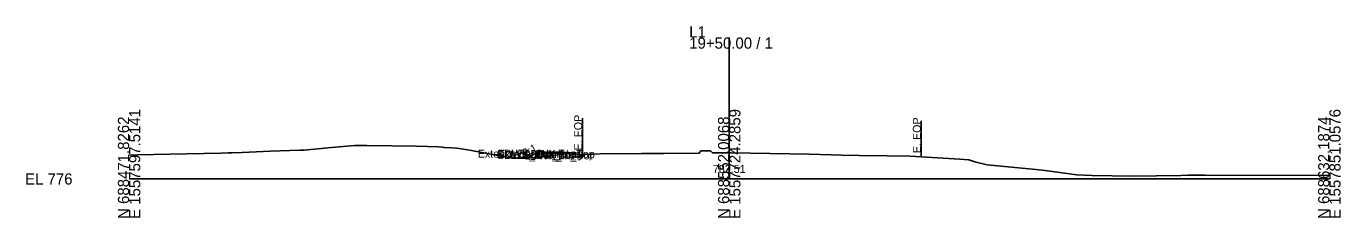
# Model space of a CAD drawing. Extents: x -26 to 2603, y -3010 to 9589.
# Drawn here: x -25.7 to 302.8, y 2990.3 to 3038.2 of the extents above; entities that cross this region are included whole.
import ezdxf

# ---------------------------------------------------------------- set-up
doc = ezdxf.new("R2010")
doc.units = 0
for name, color, linetype in [('Default', 7, 'Continuous'), ('Exist Cross Section Cell', 7, 'Continuous'), ('Exist XS Center Line Elevation Label', 7, 'Continuous'), ('Exist XS Ground Line', 7, 'Continuous'), ('Prop CMT Conc Surface', 7, 'Continuous'), ('Prop CMT Concrete Structures', 7, 'Continuous'), ('Prop CMT Slope Grass', 7, 'Continuous'), ('Prop XS Earthwork Shape', 7, 'Continuous'), ('Prop XS Label Text', 7, 'Continuous'), ('Prop XS Side Slope Text', 7, 'Continuous')]:
    doc.layers.add(name, color=color, linetype=linetype)

msp = doc.modelspace()

# ---------------------------------------------------------------- linework, layer by layer
at = {"layer": 'Exist Cross Section Cell'}
for p, q in [((150, 3000), (150, 3035.36)), ((0, 3000), (150, 3000)), ((150, 3000), (300, 3000))]:
    msp.add_line(p, q, dxfattribs=at)
at = {"layer": 'Exist XS Ground Line'}
msp.add_lwpolyline([(0, 3005.97), (2.09, 3006.03), (10.18, 3006.19), (22.96, 3006.47), (24.67, 3006.49), (25.76, 3006.5), (28.27, 3006.64), (35.25, 3006.91), (42.64, 3007.18), (43.72, 3007.22), (49.64, 3007.78), (56.33, 3008.37), (57.13, 3008.38), (57.62, 3008.37), (59.39, 3008.35), (71.81, 3008.2), (77.32, 3008.02), (78.22, 3007.98), (78.77, 3007.85), (80.71, 3007.76), (81.91, 3007.73), (84.7, 3007.26), (95.78, 3005.19), (99.32, 3005.23), (101.25, 3005.36), (101.92, 3005.36), (110.8, 3006.5), (111.27, 3006.16), (111.58, 3006.16), (113.3, 3006.13), (114.1, 3006.15), (117.73, 3006.28), (128.1, 3006.35), (130.29, 3006.36), (133.55, 3006.4), (142.5, 3006.43), (142.91, 3007.03), (143.41, 3007.03), (145.33, 3007.03), (145.82, 3006.56), (150, 3006.51), (150.48, 3006.5), (169.96, 3006.22), (178.13, 3005.98), (182.52, 3005.86), (189.43, 3005.76), (195.19, 3005.68), (196.73, 3005.6), (198, 3005.53), (207.63, 3004.93), (209.89, 3004.8), (211.43, 3004.25), (214.44, 3003.54), (226.67, 3002.4), (229.01, 3002.07), (236.86, 3001.01), (240.68, 3000.9), (250.69, 3000.72), (262.92, 3000.86), (264.75, 3000.94), (269.01, 3000.93), (286.16, 3000.87), (300, 3000.94)], dxfattribs=at)
at = {"layer": 'Prop CMT Conc Surface'}
for points in [[(108, 3006.71), (103, 3006.81)], [(111.35, 3006.01), (111.35, 3006.51), (110.85, 3006.51)], [(113.35, 3006.13), (111.35, 3006.01)]]:
    msp.add_lwpolyline(points, dxfattribs=at)
at = {"layer": 'Prop CMT Concrete Structures'}
for points in [[(103, 3006.48), (103, 3006.81)], [(108, 3006.38), (103, 3006.48)], [(108, 3006.71), (108, 3006.38)], [(110.85, 3006.51), (110.85, 3005.5), (113.35, 3005.55)], [(113.35, 3005.55), (113.35, 3006.13)]]:
    msp.add_lwpolyline(points, dxfattribs=at)
at = {"layer": 'Prop CMT Slope Grass'}
for p, q in [((102.5, 3006.82), (99.32, 3005.23)), ((103, 3006.81), (102.5, 3006.82)), ((108, 3006.71), (110.85, 3006.51))]:
    msp.add_line(p, q, dxfattribs=at)
at = {"layer": 'Prop XS Earthwork Shape'}
for points in [[(102.5, 3006.82), (99.32, 3005.23), (101.25, 3005.36), (101.92, 3005.36), (110.8, 3006.5), (110.85, 3006.46), (110.85, 3006.51), (108, 3006.71), (108, 3006.38), (103, 3006.48), (103, 3006.81)], [(110.85, 3005.5), (113.35, 3005.55), (113.35, 3006.13), (111.35, 3006.01), (111.35, 3006.16), (111.27, 3006.16), (110.85, 3006.46)], [(111.35, 3006.01), (111.35, 3006.16), (111.58, 3006.16), (113.3, 3006.13), (113.35, 3006.13)]]:
    msp.add_lwpolyline(points, close=True, dxfattribs=at)
at = {"layer": 'Prop XS Label Text'}
for p, q in [((113.35, 3015.21), (113.35, 3006.21)), ((198, 3014.53), (198, 3005.53))]:
    msp.add_line(p, q, dxfattribs=at)

# ---------------------------------------------------------------- texts
at = {"layer": 'Default'}
for s, height, p in [('Exterior Boundary', 2, (87.14, 3005.31)), ('SDWK_Out_Top', 2, (91.93, 3005.31)), ('SDWK_Out_Bot', 2, (91.96, 3004.98)), ('Exterior Boundary', 2, (92.14, 3005.21)), ('SDWK_In_Top', 2, (98.55, 3005.21)), ('SDWK_In_Bot', 2, (98.58, 3004.88)), ('-', 0.0001, (0, 3000))]:
    msp.add_text(s, height=height, dxfattribs=at).set_placement(p)
at = {"layer": 'Exist Cross Section Cell'}
for s, p in [('L1', (140, 3035.36)), ('19+50.00 / 1', (140, 3032.56)), ('EL 776', (-26, 2998.6))]:
    msp.add_text(s, height=2.8, dxfattribs=at).set_placement(p)
for s, p in [('E 1557597.5141', (2.8, 2990)), ('E 1557724.2859', (152.8, 2990)), ('E 1557851.0576', (302.8, 2990)), ('N 688471.8262', (0, 2990)), ('N 688552.0068', (150, 2990)), ('N 688632.1874', (300, 2990))]:
    msp.add_text(s, height=2.8, rotation=90, dxfattribs=at).set_placement(p)
at = {"layer": 'Exist XS Center Line Elevation Label'}
msp.add_text('782.51', height=2, dxfattribs=at).set_placement((145.92, 3001.51))
at = {"layer": 'Prop XS Label Text'}
for p in [(113.25, 3007.13), (197.9, 3006.46)]:
    msp.add_text('E. EOP', height=2, rotation=90, dxfattribs=at).set_placement(p)
at = {"layer": 'Prop XS Side Slope Text'}
msp.add_text('2:1', height=2, rotation=26.5651, dxfattribs=at).set_placement((98.88, 3005.41))

doc.saveas('drawing.dxf')
